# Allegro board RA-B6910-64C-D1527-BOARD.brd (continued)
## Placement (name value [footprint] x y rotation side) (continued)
C654  105  [C0402]  96.82 83.72 270 bottom
C655  104  [C0402]  91.87 94.16 90 bottom
C656  104  [C0402]  96.57 91.24 0 bottom
C657  103  [C0402]  105.08 90.86 0 bottom
C658  10uf/6.3V  [C0603]  102.92 86.84 0 bottom
C659  105  [C0402]  99.11 81.46 0 bottom
C660  105  [C0402]  99.11 82.47 0 bottom
C661  105  [C0402]  94.53 86.03 270 bottom
C662  105  [C0402]  95.42 89.84 90 bottom
C663  105  [C0402]  116.38 83.74 0 bottom
C664  105  [C0402]  100.1 87.55 0 bottom
C665  105  [C0402]  97.07 88.44 90 bottom
C666  105  [C0402]  96.69 86.41 180 bottom
C667  105  [C0402]  95.42 87.68 90 bottom
C668  105  [C0402]  92.63 87.1 180 bottom
C669  105  [C0402]  95.8 84.51 270 bottom
C670  105  [C0402]  98.73 86.33 0 bottom
C671  105  [C0402]  116.38 82.6 0 bottom
C672  105  [C0402]  99.11 83.49 0 bottom
C673  104  [C0402]  99.11 80.44 0 bottom
C674  22uF/6.3V  [C0603]  83.99 73.58 0 bottom
C675  22uF/6.3V  [C0603]  83.99 79.68 0 bottom
C676  22uF/6.3V  [C0603]  83.99 78.16 0 bottom
C677  22uF/6.3V  [C0603]  83.99 76.63 0 bottom
C678  22uF/6.3V  [C0603]  83.99 75.11 0 bottom
C679  104  [C0402]  101.9 138.35 0 top
C680  104  [C0402]  113.97 137.47 180 bottom
C681  104  [C0402]  111.17 106.1 0 bottom
C682  104  [C0402]  122.86 105.08 180 bottom
C683  104  [C0402]  102.41 130.73 0 top
C684  104  [C0402]  113.84 129.72 180 bottom
C685  104  [C0402]  111.17 110.92 0 top
C686  104  [C0402]  122.86 111.18 180 top
C687  104  [C0402]  111.17 103.56 0 top
C688  104  [C0402]  122.86 102.03 180 bottom
C689  104  [C0402]  134.41 68.5 0 top
C690  104  [C0402]  125.78 68.76 0 top
C691  104  [C0402]  125.78 68.76 0 bottom
C692  104  [C0402]  137.71 67.62 180 bottom
C693  104  [C0402]  74.34 36.25 0 top
C694  104  [C0402]  64.18 35.1 180 top
C695  104  [C0402]  124 65.71 270 top
C696  104  [C0402]  121.84 56.31 90 top
C697  104  [C0402]  126.28 105.84 180 top
C698  104  [C0402]  127.05 110.41 270 top
C699  104  [C0402]  137.46 106.35 0 top
C700  104  [C0402]  126.79 122.1 90 top
C701  104  [C0402]  146.22 77.39 270 top
C702  104  [C0402]  146.22 65.71 90 top
C703  104  [C0402]  150.8 76.38 270 bottom
C704  104  [C0402]  151.81 65.71 90 top
C713  220nF/16V  [C0402]  196.52 131.88 0 top
C714  220nF/16V  [C0402]  196.52 132.89 0 top
C715  220nF/16V  [C0402]  196.52 126.8 0 top
C716  220nF/16V  [C0402]  196.52 127.81 0 top
C717  220nF/16V  [C0402]  196.52 121.72 0 top
C718  220nF/16V  [C0402]  196.52 122.73 0 top
C719  220nF/16V  [C0402]  195.25 116.64 0 top
C720  220nF/16V  [C0402]  195.25 117.65 0 top
C721  220nF/16V  [C0402]  195.25 110.29 0 top
C722  220nF/16V  [C0402]  195.25 111.3 0 top
C723  220nF/16V  [C0402]  195.25 105.21 0 top
C724  220nF/16V  [C0402]  195.25 106.22 0 top
C725  220nF/16V  [C0402]  195.25 100.13 0 top
C726  220nF/16V  [C0402]  195.25 101.14 0 top
C727  220nF/16V  [C0402]  195.5 95.05 0 top
C728  220nF/16V  [C0402]  195.5 96.06 0 top
C729  10uf/6.3V  [C0603]  68.88 30.79 270 top
C730  103  [C0402]  200.58 139.88 0 top
C731  103  [C0402]  200.58 135.05 0 top
C732  103  [C0402]  194.23 137.59 0 bottom
C733  103  [C0402]  200.58 131.24 0 top
C734  103  [C0402]  200.58 138.86 0 top
C735  103  [C0402]  194.23 141.15 0 bottom
C736  103  [C0402]  194.23 140.13 0 bottom
C737  103  [C0402]  200.58 136.07 0 top
C738  103  [C0402]  194.23 138.61 0 bottom
C739  103  [C0402]  200.58 132.26 0 top
C740  103  [C0402]  194.23 136.07 0 bottom
C741  103  [C0402]  194.23 135.05 0 bottom
C742  103  [C0402]  128.06 110.41 270 bottom
C743  105  [C0402]  129.08 110.41 270 bottom
C744  103  [C0402]  91.23 161.72 90 bottom
C745  105  [C0402]  92.25 161.72 90 bottom
C746  X  [C0402]  119.43 16.31 270 bottom
C747  X  [C0402]  166.67 29.9 270 bottom
C748  X  [C0402]  58.47 16.82 270 bottom
C749  47uF/6.3V  [C0805]  139.37 31.42 270 bottom
C750  47uF/6.3V  [C0805]  120.95 30.53 270 bottom
C751  47uF/6.3V  [C0805]  57.32 39.93 90 top
C752  47uF/6.3V  [C0805]  59.61 39.93 90 top
C753  100uF/6.3V  [C1206]  71.29 30.53 270 bottom
C756  100uF/6.3V  [C1206]  73.83 30.53 270 bottom
C757  X  [C0603]  87.8 138.99 90 bottom
C758  10uF/6.3V  [C0402]  58.85 145.97 180 top
C759  104  [C0402]  58.85 144.96 0 top
C760  104  [C0402]  58.85 143.94 0 top
C761  104  [C0402]  96.19 81.84 180 bottom
C762  104  [C0402]  95.17 82.86 180 bottom
C763  104  [C0402]  93.06 89.21 270 bottom
C764  X  [C0603]  122.86 144.32 180 bottom
C765  X  [C0603]  82.22 119.8 180 top
C767  105  [C0402]  96.82 48.44 90 top
C768  0.1uF/25V  [C0402]  107.62 48.44 90 top
C769  0.1uF/25V  [C0402]  133.65 37.39 0 top
C770  105  [C0402]  133.65 38.4 0 top
C771  105  [C0402]  125.14 45.01 90 top
C772  0.1uF/25V  [C0402]  126.29 45.01 90 top
C773  105  [C0402]  128.32 48.69 270 top
C774  0.1uF/25V  [C0402]  129.46 48.69 270 top
C775  105  [C0402]  85.65 43.36 0 top
C776  0.1uF/25V  [C0402]  85.65 44.37 0 top
C777  105  [C0402]  58.21 30.15 0 top
C778  0.1uF/25V  [C0402]  58.21 29.01 0 top
C779  10uF/25V  [C0805]  189.02 12.37 90 top
C780  10uF/25V  [C0805]  189.02 12.37 90 bottom
C781  104  [C0603]  187.12 12.37 90 top
C783  104  [C0603]  183.18 10.47 180 bottom
C784  X  [C0603]  184.07 19.23 270 top
C785  105  [C0603]  182.67 19.23 90 top
C786  X  [C0603]  188.64 7.54 270 top
C787  103  [C0603]  181.28 19.23 90 top
C788  22uF/6.3V  [C0603]  172.64 7.54 0 bottom
C789  22uF/6.3V  [C0603]  172.64 9.07 0 bottom
C790  X  [C0603]  172.64 4.5 0 bottom
C791  104  [C0603]  172.64 6.02 0 bottom
C792  22UF  [C0603]  13.76 48.18 270 bottom
C793  22UF  [C0603]  15.92 48.18 270 bottom
C794  10uf/6.3V  [C0603]  12.37 51.61 90 bottom
C795  10uf/6.3V  [C0603]  13.76 51.61 90 bottom
C796  10uf/6.3V  [C0603]  12.37 48.18 270 bottom
C797  22UF  [C0603]  8.68 87.81 90 bottom
C798  22UF  [C0603]  20.11 86.41 90 bottom
C799  22UF  [C0603]  24.81 44.63 270 bottom
C800  22UF  [C0603]  26.72 44.63 270 bottom
C801  22UF  [C0603]  24.43 86.41 90 bottom
C802  22UF  [C0603]  6.4 87.81 90 bottom
C803  22UF  [C0603]  22.91 44.63 270 bottom
C804  22UF  [C0603]  13 44.63 270 bottom
C805  180P  [C0402]  97.58 159.56 90 top
C806  22uF  [C0805]  101.9 153.98 0 bottom
C807  104  [C0603]  101.9 156.13 0 top
C808  10uF  [C1206]  101.9 153.98 0 top
C809  22uF  [C0805]  101.9 156.26 0 bottom
C810  X  [C0603]  111.81 161.72 0 top
C811  104  [C0603]  111.17 159.31 270 top
C812  105  [C0603]  112.57 159.31 270 top
C813  104  [C0603]  107.87 156.13 180 top
C814  10uF  [C1206]  107.87 153.98 180 top
C815  22uF  [C0805]  107.87 156.13 180 bottom
C816  10uF/6.3V  [C0402]  46.27 134.8 270 top
C817  100P  [C0402]  48.81 134.8 270 top
CD1  100uf/25V  [CDNCC_6M6X7M7]  189.02 121.72 0 top
CD2  100uf/25V  [CDNCC_6M6X7M7]  189.02 129.08 0 top
CD3  100uf/25V  [CDNCC_6M6X7M7]  190.93 136.58 0 top
CD4  330uf/16V  [CDNCC_10M30X12M2]  194.48 26.85 0 top
CD6  220uF/25V  [CDNCC_0810]  191.05 46.79 90 top
CD7  220uF/25V  [CDNCC_0810]  168.19 158.42 0 top
CD8  330uF/2V  [CDRUB_7M3X4M3]  109.65 28.88 90 bottom
CD9  330uF/2V  [CDRUB_7M3X4M3]  97.46 29.13 90 bottom
CD10  220uF/25V  [CDNCC_0810]  95.68 7.04 90 top
CD11  220uF/25V  [CDNCC_0810]  106.6 7.04 90 top
CD12  330uF/2V  [CDRUB_7M3X4M3]  131.87 28.25 90 bottom
CD13  330uF/2V  [CDRUB_7M3X4M3]  144.06 41.58 180 bottom
CD14  330uF/2V  [CDRUB_7M3X4M3]  144.06 48.06 180 bottom
CD16  330uF/2V  [CDRUB_7M3X4M3]  56.43 50.25 90 top
CD17  330uF/2V  [CDRUB_7M3X4M3]  87.04 32.94 90 bottom
CD18  330uF/2V  [CDRUB_7M3X4M3]  80.69 32.82 90 bottom
CD19  220uF/25V  [CDNCC_0810]  84.5 7.04 90 top
CD20  220uF/25V  [CDNCC_0810]  172.13 6.78 180 top
COUPON1  -  [COUPON]  17.45 150.55 0 top
COUPON2  -  [COUPON]  17.57 17.45 0 top
COUPON3  -  [COUPON]  147.87 3.86 0 top
COUPON4  -  [COUPON]  196.52 154.1 0 top
D1  LS_SP190YG84_5  [LED_SMT0603]  159.56 92.76 180 top
D2  LS_SP190YG84_5  [LED_SMT0603]  94.28 127.81 270 top
D3  LS_SP190YG84_5  [LED_SMT0603]  93.01 155.75 180 top
D4  LS_SP190YG84_5  [LED_SMT0603]  138.22 70.92 0 top
D5  LS_SP190YG84_5  [LED_SMT0603]  138.22 68.89 0 top
D6  LS_SP190YG84_5  [LED_SMT0603]  138.22 74.98 0 top
D7  LS_SP190YG84_5  [LED_SMT0603]  138.22 72.95 0 top
D8  LS_SP190YG84_5  [LED_SMT0603]  67.61 137.85 180 top
D9  LS_SP190YG84_5  [LED_SMT0603]  67.61 136.07 180 top
D10  LS_SP190YG84_5  [LED_SMT0603]  67.61 134.29 180 top
D11  LS_SP190YG84_5  [LED_SMT0603]  67.61 132.51 180 top
D12  LS_SP190YG84_5  [LED_SMT0603]  67.61 130.73 180 top
D13  LS_SP190YG84_5  [LED_SMT0603]  67.61 128.96 180 top
D14  LS_SP190YG84_5  [LED_SMT0603]  67.61 127.18 180 top
D15  LS_SP190YG84_5  [LED_SMT0603]  67.61 125.4 180 top
D16  LS_SP190YG84_5  [LED_SMT0603]  60.75 149.28 270 top
D17  LS_SP190YG84_5  [LED_SMT0603]  64.94 149.15 270 top
D18  LS_SP190YG84_5  [LED_SMT0603]  68.12 149.15 270 top
D20  LS_SP190YG84_5  [LED_SMT0603]  190.8 55.55 270 top
D21  BAT54CLT1  [SOT_23]  152.07 23.17 0 bottom
D30  LS_SP190YG84_5  [LED_SMT0603]  135.94 133.27 0 top
D31  MBR0530T1G  [SOD_123]  161.84 103.91 270 top
D32  MBR0530T1G  [SOD_123]  159.94 103.91 270 top
FD1  -  [MARK]  20.62 145.34 0 top
FD3  -  [MARK]  20.62 145.34 180 bottom
FD4  -  [MARK]  177.59 157.02 180 bottom
FD5  -  [MARK]  154.1 10.85 180 bottom
FD6  -  [MARK]  11.6 17.07 180 bottom
FD10  -  [MARK]  179.12 151.56 0 top
FD11  -  [MARK]  154.1 10.85 0 top
FD12  -  [MARK]  11.6 17.07 0 top
FD13  -  [MARK_SYMBOL]  114.35 27.61 0 top
FD14  -  [MARK_SYMBOL]  126.03 13.01 0 top
J1  -  [1125_1205G0M110P1]  77.87 157.91 0 top
J3  -  [10131758]  164.28 96.15 0 top
J4  -  [HX42003_4]  198.67 13.26 90 top
J5  PUMBus test conn  [1125_1205G0M110P1]  138.98 7.16 0 top
J7  -  [10141732]  6.47 80.4 90 top
J8  -  [10141997]  20.2 46 90 top
JP1  -  [SIP_3P]  163.65 4.75 180 top
JP2  -  [SIP_3P]  163.65 9.58 180 top
L1  90/0.15A  [L0603]  197.02 81.33 0 top
L2  90/0.15A  [L0603]  197.02 82.73 0 top
L3  100/4A  [L0805]  135.3 99.11 90 bottom
L4  100/4A  [L0805]  155.62 95.68 180 top
L5  X  [L0805]  92.76 144.96 0 bottom
L6  100/4A  [L0805]  165.91 90.86 0 top
L7  3.3uH/8.5A  [MWSA0603S]  145.46 156.9 180 top
L8  1.5uH/9A  [L_7M2X6M5X3]  199.44 46.79 270 top
L9  1.5uH/9A  [L_7M2X6M5X3]  178.1 158.04 0 top
L10  4.5uH/3A  [NR6045T100M]  170.61 147.24 0 top
L11  4.5uH/3A  [NR6045T100M]  170.35 136.83 0 top
L12  4.5uH/3A  [NR6045T100M]  157.02 57.33 0 top
L13  100/4A  [L0805]  150.41 61.9 90 bottom
L14  3.3uH/8.5A  [MWSA0603S]  157.78 66.35 0 top
L15  100/4A  [L0805]  150.54 108.76 0 bottom
L16  100/4A  [L0805]  181.4 112.98 270 top
L17  80/1.5A  [L0805]  160.45 113.97 180 bottom
L18  80/1.5A  [L0805]  160.45 120.7 180 bottom
L19  80/1.5A  [L0805]  138.48 140.77 270 bottom
L20  80/1.5A  [L0805]  160.45 116.26 180 bottom
L21  200nH/50A  [L_11M50X7M00X9M20]  108.5 29.01 270 top
L22  200nH/50A  [L_11M50X7M00X9M20]  97.07 29.01 270 top
L23  0.22uH/25A  [L_7M2X6M5X3]  124.25 6.27 0 top
L24  0.22uH/25A  [L_7M2X6M5X3]  132.89 29.01 270 top
L25  0.22uH/25A  [L_7M2X6M5X3]  144.19 39.8 0 top
L26  0.22uH/25A  [L_7M2X6M5X3]  144.19 48.69 0 top
L27  3A  [L1206]  169.21 46.15 0 top
L28  200nH/50A  [L_11M50X7M00X9M20]  85.01 29.01 270 top
L29  1.5uH/9A  [L_7M2X6M5X3]  75 29.01 270 top
L30  0.22uH/25A  [L_7M2X6M5X3]  75.99 7.81 270 top
L31  100/4A  [L0805]  125.52 124 180 bottom
L32  8.2nH/800mA  [L0603]  112.95 59.23 180 bottom
L33  8.2nH/800mA  [L0603]  114.85 75.24 180 top
L35  80/1.5A  [L0805]  58.59 145.34 0 bottom
L36  X  [L_7M2X6M5X3]  183.18 5.77 0 top
L37  100/4A  [L0805]  92.76 148.01 0 bottom
NOREF  -  []  165.03 100.87 0 top
NOREF#2  -  []  187.6 2.27 90 top
NOREF#3  -  []  241.53 61.28 90 top
NOREF#4  -  []  105.2 127.43 90 top
NOREF#5  -  []  119.96 105.85 90 top
NOREF#6  -  []  198.65 141.26 90 top
NOREF#7  -  []  201.27 147.29 90 top
NOREF#8  -  []  38.2 114.93 90 top
NOREF#9  -  []  241.53 61.28 90 top
NOREF#10  -  []  118.91 98.85 90 top
NOREF#11  -  []  145.2 26.4 90 top
NOREF#12  -  []  163.92 154.08 90 top
NOREF#13  -  []  131.87 25.09 90 top
NOREF#14  -  []  66.35 116 0 top
NOREF#15  -  []  102.86 160.71 90 top
NOREF#16  -  []  28.88 140.51 90 top
NOREF#17  -  []  128.99 97.59 0 top
NOREF#18  -  []  157.04 148.08 0 top
NOREF#19  -  []  140.3 131.96 0 top
NOREF#20  -  []  16.1 75.78 90 top
NOREF#21  -  []  157.82 85.18 0 top
NOREF#22  -  []  6.47 46 0 top
NOREF#23  -  []  106.44 134.67 0 top
NOREF#24  -  []  160.96 24.18 0 top
NOREF#25  -  []  258.79 144.45 90 top
NOREF#26  -  []  189.19 62.04 90 top
NOREF#27  -  []  138.57 160.66 270 top
NOREF#28  -  []  118.91 105.58 90 top
NOREF#29  -  []  152.98 34.73 0 top
NOREF#30  -  []  174.28 94.42 0 top
NOREF#31  -  []  58.33 25.08 0 top
NOREF#32  -  []  176.11 148.64 0 top
NOREF#33  -  []  120.17 20.13 90 top
NOREF#34  -  []  141.55 68.61 90 top
NOREF#35  -  []  113.67 15.74 90 top
NOREF#36  -  []  133.95 158.8 270 top
NOREF#37  -  []  156.46 40.56 90 top
NOREF#38  -  []  148.23 143.84 0 top
NOREF#39  -  []  102.34 2.76 0 top
NOREF#40  -  []  185.42 118.32 90 top
NOREF#41  -  []  122.45 100.6 0 top
NOREF#42  -  []  163.16 60.12 0 top
NOREF#43  -  []  168.86 6.78 0 top
NOREF#44  -  []  155.09 111.03 0 top
NOREF#45  -  []  156.94 101.67 270 top
NOREF#46  -  []  156.52 48.27 90 top
NOREF#47  -  []  184.28 96.15 90 top
NOREF#48  -  []  128.99 58.09 0 top
NOREF#49  -  []  140.91 48.06 0 top
NOREF#50  -  []  140.26 43.88 0 top
NOREF#51  -  []  113.2 104.06 90 top
NOREF#52  -  []  148.61 36.3 90 top
NOREF#53  -  []  96.7 20.63 90 top
NOREF#54  -  []  2.37 56.78 90 top
NOREF#55  -  []  106.34 137.97 90 top
NOREF#56  -  []  112.67 15.74 0 top
NOREF#57  -  []  111.96 60.25 90 top
NOREF#58  -  []  87.04 29.79 90 top
NOREF#59  -  []  16.1 47.28 90 top
NOREF#60  -  []  134.57 160.66 0 top
NOREF#61  -  []  147.38 68.6 0 top
NOREF#62  -  []  111.07 142.14 90 top
NOREF#63  -  []  109.9 130.47 90 top
NOREF#64  -  []  2.37 113.78 0 top
NOREF#65  -  []  20.2 46 90 top
NOREF#66  -  []  152.76 51.46 0 top
NOREF#67  -  []  155.89 111.03 90 top
NOREF#68  -  []  147.38 68.6 90 top
NOREF#69  -  []  165.43 65.63 0 top
NOREF#70  -  []  146.45 59.69 270 top
NOREF#71  -  []  66.35 44 90 top
NOREF#72  -  []  100.73 15.74 0 top
NOREF#73  -  []  113.2 105.46 90 top
NOREF#74  -  []  20.2 46 90 top
NOREF#75  -  []  161.43 62.95 90 top
NOREF#76  -  []  59.25 37.4 0 top
NOREF#77  -  []  129.83 24.24 0 top
NOREF#78  -  []  129.62 69.76 90 top
NOREF#79  -  []  114.06 99.12 0 top
NOREF#80  -  []  186.47 121.72 0 top
NOREF#81  -  []  188.38 136.58 0 top
NOREF#82  -  []  129.59 140.64 270 top
NOREF#83  -  []  197.38 91.73 90 top
NOREF#84  -  []  119.96 99.12 90 top
NOREF#85  -  []  32.2 46.6 90 top
NOREF#86  -  []  10.57 78.03 90 top
NOREF#87  -  []  104.19 130.35 90 top
NOREF#88  -  []  130.32 31.3 90 top
NOREF#89  -  []  113.2 110.8 90 top
NOREF#90  -  []  91.41 2.76 0 top
NOREF#91  -  []  54.14 46.45 90 top
NOREF#92  -  []  156.94 102.32 270 top
NOREF#93  -  []  186.79 42.51 0 top
NOREF#94  -  []  167.03 33.72 90 top
NOREF#95  -  []  176.41 2.52 90 top
NOREF#96  -  []  163.93 100.65 0 top
NOREF#97  -  []  197.3 143.32 90 top
NOREF#98  -  []  184.01 65.63 0 top
NOREF#99  -  []  141.55 68.61 0 top
NOREF#100  -  []  170.06 67.49 90 top
NOREF#101  -  []  89.67 15.74 90 top
NOREF#102  -  []  134.49 140.15 270 top
NOREF#103  -  []  128.99 60.63 270 top
NOREF#104  -  []  202.87 151.64 0 top
NOREF#105  -  []  176.74 144.24 90 top
NOREF#106  -  []  2.37 47.28 90 top
NOREF#107  -  []  148.61 45.19 90 top
NOREF#108  -  []  152.56 51.51 0 top
NOREF#109  -  []  185.21 94.56 90 top
NOREF#110  -  []  6.47 114.8 0 top
NOREF#111  -  []  197.38 141.26 0 top
NOREF#112  -  []  132.83 106.33 0 top
NOREF#113  -  []  163.23 56.55 90 top
NOREF#114  -  []  185.61 68.47 0 top
NOREF#115  -  []  108.1 31.93 90 top
NOREF#116  -  []  -28.47 54.87 90 top
NOREF#117  -  []  152.56 42.11 0 top
NOREF#118  -  []  163.23 18.55 90 top
NOREF#119  -  []  106.06 147.5 0 top
NOREF#120  -  []  59.08 20.13 90 top
NOREF#121  -  []  96.18 20.63 90 top
NOREF#122  -  []  181.36 146.1 90 top
NOREF#123  -  []  189.23 21.6 90 top
NOREF#124  -  []  84.5 3.76 90 top
NOREF#125  -  []  182.55 16.01 0 top
NOREF#126  -  []  165.03 100.87 0 top
NOREF#127  -  []  88.76 23.76 90 top
NOREF#128  -  []  164.81 70.03 0 top
NOREF#129  -  []  174.28 94.42 0 top
NOREF#130  -  []  10.57 97.53 90 top
NOREF#131  -  []  112.26 23.76 90 top
NOREF#132  -  []  160.22 143.84 270 top
NOREF#133  -  []  77.76 11.93 90 top
NOREF#134  -  []  63.43 19.98 90 top
NOREF#135  -  []  176.48 133.83 90 top
NOREF#136  -  []  181.78 94.42 0 top
NOREF#137  -  []  181.53 100.87 0 top
NOREF#138  -  []  175.86 138.23 0 top
NOREF#139  -  []  140.26 45.76 90 top
NOREF#140  -  []  157.19 85.78 0 top
NOREF#141  -  []  135.93 103.23 90 top
NOREF#142  -  []  129.1 134.78 0 top
NOREF#143  -  []  163.28 94.56 90 top
NOREF#144  -  []  88.3 5.2 90 top
NOREF#145  -  []  128.35 42.43 90 top
NOREF#146  -  []  20.2 46 0 top
NOREF#147  -  []  163.92 162.68 0 top
NOREF#148  -  []  142.45 59.69 0 top
NOREF#149  -  []  14.47 42.65 90 top
NOREF#150  -  []  67.04 36.16 0 top
NOREF#151  -  []  181.11 135.69 90 top
NOREF#152  -  []  151.85 99.83 0 top
NOREF#153  -  []  124.52 19.98 90 top
NOREF#154  -  []  7.49 144.68 0 top
NOREF#155  -  []  176.48 133.83 0 top
NOREF#156  -  []  139.51 133.19 0 top
NOREF#157  -  []  166.28 38.67 0 top
NOREF#158  -  []  164.92 158.42 0 top
NOREF#159  -  []  162.22 28.08 270 top
NOREF#160  -  []  23.3 133.4 0 top
NOREF#161  -  []  85.49 35.99 90 top
NOREF#162  -  []  133.62 102.03 270 top
NOREF#163  -  []  2.37 75.78 90 top
NOREF#164  -  []  115.23 105.59 90 top
NOREF#165  -  []  101.73 15.74 90 top
NOREF#166  -  []  -28.47 54.87 0 top
NOREF#167  -  []  189.23 32.1 0 top
NOREF#168  -  []  95.68 3.76 90 top
NOREF#169  -  []  99.76 25.33 90 top
NOREF#170  -  []  135.33 69.65 90 top
NOREF#171  -  []  182.52 154.54 90 top
NOREF#172  -  []  125.14 141.12 270 top
NOREF#173  -  []  197.28 89.3 0 top
NOREF#174  -  []  112.26 34.26 270 top
NOREF#175  -  []  140.3 131.96 90 top
NOREF#176  -  []  154.13 69.75 0 top
NOREF#177  -  []  10.57 57.53 90 top
NOREF#178  -  []  141.26 133.19 90 top
NOREF#179  -  []  88.67 15.74 0 top
NOREF#180  -  []  161.22 145.14 270 top
NOREF#181  -  []  105.17 142.79 0 top
NOREF#182  -  []  114.06 110.4 0 top
NOREF#183  -  []  113.83 105.58 90 top
NOREF#184  -  []  24.3 47.03 90 top
NOREF#185  -  []  108.5 33.56 270 top
NOREF#186  -  []  141.82 57.84 270 top
NOREF#187  -  []  96.18 20.63 0 top
NOREF#188  -  []  163.23 38.55 90 top
NOREF#189  -  []  189.19 62.04 90 top
NOREF#190  -  []  163.78 55.72 0 top
NOREF#191  -  []  102.34 2.76 0 top
NOREF#192  -  []  6.47 114.8 0 top
NOREF#193  -  []  189.19 62.04 0 top
NOREF#194  -  []  20.2 46 90 top
NOREF#195  -  []  119.42 25.08 0 top
NOREF#196  -  []  80.24 2.76 0 top
NOREF#197  -  []  85.01 33.56 270 top
NOREF#198  -  []  66.35 44 0 top
NOREF#199  -  []  201.19 91.73 90 top
NOREF#200  -  []  87.31 26.4 90 top
NOREF#201  -  []  199.92 91.73 0 top
NOREF#202  -  []  -1.85 114.18 0 top
NOREF#203  -  []  185.61 61.28 0 top
NOREF#204  -  []  107.58 157.57 90 top
NOREF#205  -  []  41.3 17.09 90 top
NOREF#206  -  []  141.82 55.3 0 top
NOREF#207  -  []  124.37 20.73 90 top
NOREF#208  -  []  6.47 114.8 90 top
NOREF#209  -  []  183.28 94.42 90 top
NOREF#210  -  []  137.62 22.01 0 top
NOREF#211  -  []  179.03 100.87 0 top
NOREF#212  -  []  82.99 29.02 90 top
NOREF#213  -  []  187.29 112.73 90 top
NOREF#214  -  []  117.04 60.25 0 top
NOREF#215  -  []  104.31 137.85 90 top
NOREF#216  -  []  34.38 119.38 0 top
NOREF#217  -  []  17.32 133.4 0 top
NOREF#218  -  []  160.54 158.88 270 top
NOREF#219  -  []  165.28 94.42 90 top
NOREF#220  -  []  89.34 29.14 90 top
NOREF#221  -  []  110.95 134.65 90 top
NOREF#222  -  []  147.11 69.65 0 top
NOREF#223  -  []  84.12 20.63 0 top
NOREF#224  -  []  156.41 156.5 90 top
NOREF#225  -  []  185.67 11.39 90 top
NOREF#226  -  []  152.76 42.06 0 top
NOREF#227  -  []  35.99 146.61 0 top
NOREF#228  -  []  129.62 62.49 0 top
NOREF#229  -  []  6.47 46 90 top
NOREF#230  -  []  180.69 11.39 0 top
NOREF#231  -  []  90.85 42.43 0 top
NOREF#232  -  []  103.58 157.57 0 top
NOREF#233  -  []  184.01 64.11 90 top
NOREF#234  -  []  185.62 132.48 0 top
NOREF#235  -  []  186.47 129.08 0 top
NOREF#236  -  []  108.64 20.63 90 top
NOREF#237  -  []  111.83 129.29 90 top
NOREF#238  -  []  16.1 113.78 0 top
NOREF#239  -  []  88.76 34.26 270 top
NOREF#240  -  []  165.43 65.63 90 top
NOREF#241  -  []  171.23 34.32 90 top
NOREF#242  -  []  140.91 41.58 0 top
NOREF#243  -  []  155.92 157.02 270 top
NOREF#244  -  []  154.93 66.35 0 top
NOREF#245  -  []  187.29 114 0 top
NOREF#246  -  []  129.98 115.03 90 top
NOREF#247  -  []  20.2 46 0 top
NOREF#248  -  []  56.43 47.1 90 top
NOREF#249  -  []  10.57 47.03 90 top
NOREF#250  -  []  167.81 3.48 0 top
NOREF#251  -  []  142.02 69.65 90 top
NOREF#252  -  []  6.47 46 90 top
NOREF#253  -  []  14.47 42.65 0 top
NOREF#254  -  []  133.88 16.24 90 top
NOREF#255  -  []  140.26 50.36 0 top
NOREF#256  -  []  108.12 20.63 0 top
NOREF#257  -  []  191.2 116.43 0 top
NOREF#258  -  []  122.35 141.78 0 top
NOREF#259  -  []  147.23 145.14 0 top
NOREF#260  -  []  191.1 114 0 top
NOREF#261  -  []  111.95 25.08 90 top
NOREF#262  -  []  63.28 20.73 90 top
NOREF#263  -  []  156.46 49.96 90 top
NOREF#264  -  []  16.1 78.28 90 top
NOREF#265  -  []  188.74 59.38 90 top
NOREF#266  -  []  201.19 91.73 90 top
NOREF#267  -  []  105.58 143.05 0 top
NOREF#268  -  []  57.98 53.3 90 top
NOREF#269  -  []  164.28 96.15 0 top
NOREF#270  -  []  149.11 156.5 0 top
NOREF#271  -  []  140.26 39.28 90 top
NOREF#272  -  []  95.91 32.18 90 top
NOREF#273  -  []  199.29 143.69 0 top
NOREF#274  -  []  119.57 23.93 90 top
NOREF#275  -  []  109.65 25.73 90 top
NOREF#276  -  []  156.54 158.88 0 top
NOREF#277  -  []  105.96 130.23 0 top
NOREF#278  -  []  191.05 43.51 90 top
NOREF#279  -  []  187.53 139.98 0 top
NOREF#280  -  []  44.37 142.26 0 top
NOREF#281  -  []  241.53 68.47 90 top
NOREF#282  -  []  72.94 24.24 0 top
NOREF#283  -  []  122.25 65.96 90 top
NOREF#284  -  []  97.46 25.98 90 top
NOREF#285  -  []  165.28 94.42 0 top
NOREF#286  -  []  163.78 55.72 90 top
NOREF#287  -  []  106.6 3.76 90 top
NOREF#288  -  []  106.21 130.48 90 top
NOREF#289  -  []  80.69 29.67 90 top
NOREF#290  -  []  125.14 141.12 270 top
NOREF#291  -  []  190.36 26.85 0 top
NOREF#292  -  []  6.47 46 90 top
NOREF#293  -  []  151.25 100.37 0 top
NOREF#294  -  []  66.35 44 0 top
NOREF#295  -  []  141.28 69.66 0 top
NOREF#296  -  []  91.41 2.76 0 top
NOREF#297  -  []  70.81 32.49 90 top
NOREF#298  -  []  2.37 78.28 90 top
NOREF#299  -  []  20.2 114.8 90 top
NOREF#300  -  []  2.37 100.78 90 top
NOREF#301  -  []  113.83 98.85 90 top
NOREF#302  -  []  140.97 24.18 0 top
NOREF#303  -  []  67.71 35.59 0 top
NOREF#304  -  []  -3.85 140.38 0 top
NOREF#305  -  []  133.95 156.26 0 top
NOREF#306  -  []  185.42 125.68 90 top
NOREF#307  -  []  124.21 135.25 0 top
NOREF#308  -  []  142.61 156.9 0 top
NOREF#309  -  []  24.3 78.03 90 top
NOREF#310  -  []  119.96 109.75 90 top
NOREF#311  -  []  105.05 135.3 0 top
NOREF#312  -  []  186.79 42.51 0 top
NOREF#313  -  []  156.35 102.93 0 top
NOREF#314  -  []  118.91 105.57 90 top
NOREF#315  -  []  163.93 100.65 0 top
NOREF#316  -  []  80.24 2.76 0 top
NOREF#317  -  []  152.32 75.36 90 top
NOREF#318  -  []  36.37 140.51 0 top
NOREF#319  -  []  58.48 23.93 90 top
NOREF#320  -  []  126.88 118.13 0 top
NOREF#321  -  []  32.2 114.2 90 top
NOREF#322  -  []  79.14 35.87 90 top
NOREF#323  -  []  133.62 62.49 270 top
NOREF#324  -  []  117.31 59.2 90 top
NOREF#325  -  []  110.02 137.96 90 top
NOREF#326  -  []  155.92 154.48 0 top
NOREF#327  -  []  136.19 69.66 90 top
NOREF#328  -  []  49.45 138.26 90 top
NOREF#329  -  []  128.57 74.59 0 top
NOREF#330  -  []  129.62 96.95 0 top
NOREF#331  -  []  128.67 2.77 90 top
NOREF#332  -  []  134.17 24.44 90 top
NOREF#333  -  []  181.28 10.76 90 top
NOREF#334  -  []  75.48 16.24 0 top
NOREF#335  -  []  129.05 105.75 0 top
NOREF#336  -  []  108.12 20.63 90 top
NOREF#337  -  []  76.99 16.24 90 top
NOREF#338  -  []  132.38 16.24 0 top
NOREF#339  -  []  171.38 33.57 90 top
NOREF#340  -  []  176.14 128.98 90 top
NOREF#341  -  []  134.66 11.93 90 top
NOREF#342  -  []  111.45 142.12 90 top
NOREF#343  -  []  84.63 20.63 90 top
NOREF#344  -  []  144.45 37.4 90 top
NOREF#345  -  []  197.28 89.3 90 top
NOREF#346  -  []  23.3 133.4 0 top
NOREF#347  -  []  179.28 94.42 0 top
NOREF#348  -  []  146.49 75.37 90 top
NOREF#349  -  []  133.3 69.77 90 top
NOREF#350  -  []  128.57 73.94 90 top
NOREF#351  -  []  196.88 89.73 0 top
NOREF#352  -  []  24.3 75.53 90 top
NOREF#353  -  []  195.94 42.37 0 top
NOREF#354  -  []  166.43 37.52 90 top
NOREF#355  -  []  187.33 133.18 90 top
NOREF#356  -  []  114.06 105.85 0 top
NOREF#357  -  []  176.74 144.24 0 top
NOREF#358  -  []  183.28 94.42 90 top
NOREF#359  -  []  165.03 100.87 0 top
NOREF#360  -  []  105.2 149.66 270 top
NOREF#361  -  []  -32.7 17.09 0 top
NOREF#362  -  []  34.97 133.53 270 top
NOREF#363  -  []  168.41 57.58 90 top
NOREF#364  -  []  122.35 133.02 0 top
NOREF#365  -  []  156.52 38.88 90 top
NOREF#366  -  []  84.12 20.63 90 top
NOREF#367  -  []  165.28 94.42 0 top
NOREF#368  -  []  127.45 114.35 90 top
NOREF#369  -  []  48.81 137.63 90 top
NOREF#370  -  []  117.31 59.2 0 top
NOREF#371  -  []  165.03 100.87 0 top
NOREF#372  -  []  10.57 75.53 90 top
NOREF#373  -  []  201.27 148.81 0 top
NOREF#374  -  []  185.62 125.12 0 top
NOREF#375  -  []  164.28 96.15 90 top
OSC1  50MHZ  [SMD5X7]  142.92 100 0 top
OSC2  24MHz  [D3SX24E000008E]  140.38 134.29 270 top
OSC3  25.000625MHz  [OSC_SMD3M2X2M5]  170.73 125.65 0 top
OSC4  25.000625MHz  [OSC_SMD3M2X2M5]  119.43 69.01 0 top
OSC5  25.000625MHz  [OSC_SMD3M2X2M5]  108 108.76 270 top
OSC6  25MHZ  [SMD5X7]  64.94 142.8 0 top
Q1  SM12  [SOT_23]  198.42 86.03 180 bottom
Q2  2N7002  [SOT_23]  159.94 96.32 270 top
Q3  2N7002  [SOT_23]  159.94 96.32 270 bottom
Q4  SM12  [SOT_23]  198.42 86.03 0 top
Q5  2N7002  [SOT_23]  93.01 152.45 180 top
Q6  2N7002  [SOT_23]  91.11 126.42 270 bottom
Q7  MMST3906  [SOT_23]  60.37 149.15 270 bottom
Q8  MMST3906  [SOT_23]  68.25 149.15 90 bottom
Q9  MMST3906  [SOT_23]  64.31 149.15 90 bottom
Q10  MMBT3904LT1G  [SOT_23]  14.65 91.36 270 bottom
Q11  MMBT3904LT1G  [SOT_23]  14.27 85.78 180 bottom
Q14  MMST3906  [SOT_23]  170.61 98.48 90 bottom
Q15  MMBT3904LT1G  [SOT_23]  189.15 147.37 270 top
Q16  MMBT3904LT1G  [SOT_23]  193.21 147.37 270 top
Q17  MMBT3904LT1G  [SOT_23]  189.15 147.37 270 bottom
Q18  MMBT3904LT1G  [SOT_23]  193.21 147.37 270 bottom
Q19  MMBT3904LT1G  [SOT_23]  127.94 160.58 90 bottom
Q20  MMBT3904LT1G  [SOT_23]  127.94 160.58 270 top
Q21  MMBT3904LT1G  [SOT_23]  123.87 160.58 90 top
Q22  MMBT3904LT1G  [SOT_23]  123.87 160.58 270 bottom
Q23  MMBT3904LT1G  [SOT_23]  95.17 121.59 90 bottom
Q24  MMBT3904LT1G  [SOT_23]  86.28 117.4 270 bottom
Q25  MMBT3904LT1G  [SOT_23]  82.34 117.4 270 bottom
Q26  MMBT3904LT1G  [SOT_23]  95.04 126.42 90 bottom
Q27  MMBT3904LT1G  [SOT_23]  179.12 68.63 0 bottom
Q28  MMBT3904LT1G  [SOT_23]  179.12 64.57 180 bottom
Q29  MMBT3904LT1G  [SOT_23]  156 74.6 0 bottom
Q30  MMBT3904LT1G  [SOT_23]  160.7 74.6 0 bottom
Q33  MMBT3904LT1G  [SOT_23]  78.66 160.07 180 bottom
Q34  MMBT3904LT1G  [SOT_23]  95.17 151.82 180 bottom
Q35  2N7002  [SOT_23]  118.79 152.83 90 top
Q36  2N7002  [SOT_23]  76.88 118.15 270 top
Q37  MMBT3904LT1G  [SOT_23]  58.34 134.8 180 top
Q38  MMBT3904LT1G  [SOT_23]  58.34 130.73 0 top
Q39  MMBT3904LT1G  [SOT_23]  50.08 131.12 270 top
Q40  APL431LAAC_TRG  [SOT_23]  45.89 131.12 270 top
Q41  MMBT3904LT1G  [SOT_23]  47.67 149.53 270 top
R1  1K  [R0402]  195.5 85.52 90 top
R2  560  [R0402]  160.32 92.51 180 bottom
R3  33  [R0402]  199.94 83.49 180 bottom
R4  10K_1%  [R0402]  157.91 93.52 0 bottom
R5  10K_1%  [R0402]  160.32 93.52 180 bottom
R6  33  [R0402]  157.91 92.51 0 bottom
R7  1K  [R0402]  199.94 82.22 180 top
R8  560  [R0402]  95.55 129.21 0 bottom
R9  33  [R0402]  201.34 85.27 90 top
R10  560  [R0402]  93.01 157.53 180 top
R11  22  [R0402]  89.45 125.65 90 top
R12  22  [R0402]  86.41 147.5 90 bottom
R13  4.7K  [R0402]  87.42 147.5 270 bottom
R14  4.7K  [R0402]  90.47 125.65 270 top
R15  330  [R0402]  139.49 71.17 180 bottom
R16  330  [R0402]  141.65 71.17 0 bottom
R17  330  [R0402]  139.49 75.24 180 bottom
R18  330  [R0402]  139.49 73.2 180 bottom
R19  33_1%  [R0402]  61.77 37.14 0 top
R20  33_1%  [R0402]  61.77 36.12 0 top
R21  1K_1%  [R0402]  148.76 91.24 270 top
R22  1K_1%  [R0402]  143.68 91.24 270 top
R23  1K_1%  [R0402]  151.68 96.19 0 top
R24  2.49K_1%  [R0402]  154.48 90.73 0 top
R25  1K_1%  [R0402]  152.83 93.9 270 top
R26  0  [R0402]  146.73 91.24 270 top
R27  0  [R0402]  145.72 91.24 270 top
R28  0  [R0402]  151.68 97.21 0 top
R29  0  [R0402]  154.61 93.78 0 top
R30  0  [R0402]  150.8 93.9 270 top
R31  7.15K_1%  [R0402]  154.48 91.75 180 top
R32  1K_1%  [R0402]  152.83 91.24 270 top
R33  1K_1%  [R0402]  143.68 93.9 270 top
R34  3.3K_1%  [R0402]  163.75 129.72 180 top
R35  7.15K_1%  [R0402]  172.26 129.72 90 top
R36  1K_1%  [R0402]  149.78 93.9 270 top
R37  0  [R0402]  149.78 91.24 270 top
R38  0  [R0402]  146.73 93.9 270 top
R39  0  [R0402]  161.21 131.75 0 top
R40  0  [R0402]  169.21 129.72 90 top
R41  0  [R0402]  147.75 93.9 270 top
R42  620_1%  [R0402]  150.8 91.24 90 top
R43  620_1%  [R0402]  144.7 93.9 90 top
R44  1K_1%  [R0402]  163.75 131.75 0 top
R45  820_1%  [R0402]  171.24 129.72 270 top
R46  X  [R0402]  167.43 120.96 90 bottom
R47  X  [R0402]  164.38 120.96 90 bottom
R48  33  [R0402]  82.47 108.76 270 bottom
R49  33  [R0402]  166.42 120.96 90 bottom
R50  33  [R0402]  165.4 120.96 90 bottom
R51  0  [R0402]  140.25 114.61 270 bottom
R52  33  [R0402]  88.06 142.04 0 bottom
R53  33  [R0402]  137.56 114.35 0 bottom
R54  33  [R0402]  149.4 98.22 0 top
R55  4.7K  [R0402]  153.46 101.91 180 bottom
R56  33  [R0402]  157.02 100.89 180 bottom
R57  22  [R0402]  148.51 103.94 0 top
R58  33  [R0402]  157.02 101.91 180 bottom
R59  0  [R0402]  82.72 150.8 270 top
R60  33  [R0402]  71.17 136.07 180 bottom
R61  33  [R0402]  94.28 130.86 0 top
R63  33  [R0402]  96.69 101.02 270 bottom
R64  0  [R0402]  83.74 150.8 270 top
R65  33  [R0402]  94.28 134.93 0 top
R66  33  [R0402]  71.17 139.12 180 bottom
R67  33  [R0402]  71.17 140.13 180 bottom
R68  4.7K  [R0402]  71.17 138.1 180 bottom
R69  4.7K  [R0402]  71.17 133.02 180 bottom
R70  10K_1%  [R0402]  83.36 125.65 90 bottom
R71  X  [R0402]  94.28 131.88 0 top
R72  0  [R0402]  94.28 132.89 0 top
R73  10K_1%  [R0402]  80.44 129.85 270 bottom
R74  0  [R0402]  71.17 135.05 180 bottom
R75  10K_1%  [R0402]  71.04 131.62 180 bottom
R76  10K_1%  [R0402]  71.04 129.59 180 bottom
R77  10K_1%  [R0402]  85.39 125.65 270 bottom
R78  10K_1%  [R0402]  81.45 129.85 270 bottom
R79  0  [R0402]  71.17 137.08 180 bottom
R80  0  [R0402]  71.17 134.04 180 bottom
R81  33  [R0402]  94.28 133.91 0 bottom
R82  0  [R0402]  71.04 130.61 180 bottom
R83  0  [R0402]  88.44 125.65 270 top
R84  0  [R0402]  79.29 125.65 270 top
R85  0  [R0402]  84.37 125.65 270 top
R86  0  [R0402]  86.41 125.65 270 top
R87  0  [R0402]  87.42 125.65 270 top
R88  0  [R0402]  75.23 125.65 270 top
R89  0  [R0402]  76.25 125.65 270 top
R90  0  [R0402]  77.26 125.65 270 top
R91  0  [R0402]  78.28 125.65 270 top
R92  0  [R0402]  80.31 125.65 270 top
R93  0  [R0402]  81.33 125.65 270 top
R94  10K_1%  [R0402]  82.34 125.65 270 top
R95  10K_1%  [R0402]  77.9 129.85 270 bottom
R96  560  [R0402]  64.05 137.85 0 top
R97  560  [R0402]  64.05 136.07 0 top
R98  33  [R0402]  103.81 124.51 90 bottom
R99  560  [R0402]  64.05 134.29 0 top
R100  560  [R0402]  64.05 132.51 0 top
R101  560  [R0402]  64.05 130.73 0 top
R102  560  [R0402]  64.05 128.96 0 top
R103  560  [R0402]  64.05 127.18 0 top
R104  560  [R0402]  64.05 125.4 0 top
R105  1K  [R0402]  79.42 129.85 270 bottom
R106  4.7K  [R0402]  91.99 136.96 0 bottom
R107  4.7K  [R0402]  91.99 138.35 0 bottom
R108  1K  [R0402]  82.47 129.85 270 bottom
R109  10K_1%  [R0402]  79.68 150.8 90 top
R110  10K_1%  [R0402]  77.39 150.8 90 top
R111  10K_1%  [R0402]  73.07 150.8 90 top
R112  X  [R0402]  81.71 150.8 90 top
R113  22  [R0402]  91.99 135.94 0 bottom
R114  100  [R0402]  74.09 150.8 90 top
R115  33  [R0402]  75.36 150.8 90 top
R116  100  [R0402]  78.41 150.8 90 top
R117  100  [R0402]  80.69 150.8 90 top
R118  330  [R0402]  59.1 150.29 90 top
R119  1K  [R0402]  62.28 148.01 90 top
R120  1K  [R0402]  59.1 148.13 90 top
R121  330  [R0402]  63.42 148.01 270 top
R122  1K  [R0402]  69.64 150.17 90 top
R123  1K  [R0402]  69.64 148.01 90 top
R124  330  [R0402]  66.59 148.13 270 top
R125  1K  [R0402]  63.42 150.17 270 top
R126  1K  [R0402]  62.28 150.17 90 top
R127  0  [R0402]  10.21 69.52 270 bottom
R129  0  [R0402]  19.35 43.36 270 bottom
R131  0  [R0402]  18.21 43.36 270 bottom
R133  4.7K  [R0402]  15.16 88.44 0 bottom
R134  4.7K  [R0402]  14.27 94.41 0 bottom
R137  1K  [R0402]  12.62 78.66 90 bottom
R138  1K  [R0402]  13.13 82.73 90 bottom
R139  X  [R0402]  24.3 68.25 180 bottom
R140  X  [R0402]  21.89 47.93 90 bottom
R142  0  [R0402]  26.84 49.2 0 bottom
R145  0  [R0402]  122.22 112.95 0 top
R146  0  [R0402]  124.51 112.95 180 top
R147  0  [R0402]  122.22 116 180 top
R148  0  [R0402]  122.22 117.02 180 top
R149  0  [R0402]  122.22 120.07 180 top
R150  0  [R0402]  122.22 119.05 180 top
R151  0  [R0402]  111.3 127.56 270 bottom
R152  0  [R0402]  117.27 141.4 0 top
R159  0  [R0603]  168.96 94.54 90 bottom
R160  0  [R0603]  170.35 94.54 90 bottom
R161  0  [R0603]  171.75 94.54 90 bottom
R162  0  [R0603]  173.15 94.54 90 bottom
R163  X  [R0402]  178.99 90.73 270 top
R164  1K  [R0402]  182.04 101.02 270 bottom
R165  0  [R0402]  180.01 90.73 270 top
R166  330  [R0402]  189.28 55.55 90 top
R167  1K  [R0402]  167.81 97.97 270 bottom
R168  1K  [R0402]  166.8 97.97 270 bottom
R169  0  [R0402]  183.94 66.6 0 bottom
R170  0  [R0402]  183.94 67.62 0 bottom
R171  0  [R0402]  183.94 65.58 0 bottom
R172  0  [R0402]  192.96 80.44 0 top
R173  0  [R0402]  192.96 81.46 180 top
R174  0  [R0402]  184.7 80.95 0 top
R175  0  [R0402]  192.96 84.89 180 top
R176  0  [R0402]  185.47 84.25 0 top
R177  0  [R0402]  182.92 86.03 0 top
R178  0  [R0402]  185.34 87.17 0 top
R179  0  [R0402]  192.96 93.65 180 top
R180  0  [R0402]  187.88 92.41 180 top
R181  0  [R0402]  193.34 96.83 180 top
R182  0  [R0402]  184.2 98.22 0 bottom
R183  0  [R0402]  189.28 98.22 180 top
R184  0  [R0402]  184.2 99.24 0 bottom
R185  10K_1%  [R0402]  193.34 97.84 0 top
R186  0  [R0402]  189.28 99.24 180 top
R187  0  [R0402]  184.2 100.25 0 bottom
R188  0  [R0402]  184.2 101.27 0 bottom
R189  0  [R0402]  184.2 102.29 0 bottom
R190  0  [R0402]  193.09 101.91 0 top
R191  10K_1%  [R0402]  193.09 102.92 180 top
R192  0  [R0402]  185.34 104.7 180 top
R193  0  [R0402]  185.34 105.72 180 top
R194  560  [R0402]  185.34 109.78 180 top
R195  0  [R0402]  185.34 106.73 0 top
R196  560  [R0402]  185.34 110.8 0 top
R197  0  [R0402]  185.34 108.76 0 top
R198  0  [R0402]  185.34 107.75 180 top
R199  560  [R0402]  185.34 111.81 0 top
R200  0  [R0805]  31.16 30.91 180 top
R201  X  [R0402]  27.73 27.86 270 top
R202  10K_1%  [R0603]  35.1 31.04 180 top
R203  100K_1%  [R0603]  31.03 27.86 90 top
R204  X  [R0402]  28.75 27.86 90 top
R205  0  [R0402]  29.76 27.86 90 top
R206  10K_1%  [R0603]  35.1 33.83 0 top
R207  10K_1%  [R0603]  136.95 161.6 0 top
R208  0  [R0402]  134.16 160.71 0 bottom
R209  10K_1%  [R0603]  133.78 158.04 180 bottom
R210  3.01K_1%  [R0603]  133.9 161.6 180 top
R211  3.01K_1%  [R0603]  133.78 156.64 0 bottom
R212  X  [R1206]  142.67 154.86 180 bottom
R213  10K_1%  [R0402]  193.34 33.45 90 top
R214  0  [R0402]  192.32 33.45 270 top
R215  5.6K_1%  [R0603]  189.15 33.45 0 top
R216  X  [R0805]  186.23 30.15 0 top
R217  300_1%  [R0603]  186.23 32.06 0 top
R218  300  [R0603]  189.15 36.25 180 top
R219  2.2K_1%  [R0603]  189.15 34.85 180 top
R220  10K_1%  [R0402]  194.36 33.45 90 top
R221  10K  [R0603]  189.15 37.64 0 top
R222  80.6K_1%  [R0603]  189.15 39.04 180 top
R223  0  [R0603]  185.34 39.17 180 top
R224  1  [R0805]  200.2 40.06 0 top
R225  10K_1%  [R0402]  189.78 154.99 180 top
R226  3.3K_1%  [R0402]  191.05 152.71 90 top
R227  5.6K_1%  [R0603]  187.37 152.71 90 top
R228  300  [R0603]  188.77 152.71 270 top
R229  15K_1%  [R0402]  190.04 152.71 270 top
R230  10K  [R0603]  184.58 152.71 90 top
R231  80.6K_1%  [R0603]  183.18 152.71 270 top
R232  0  [R0603]  182.8 156.64 180 bottom
R233  X  [R0805]  181.66 161.72 180 bottom
R234  0  [R0402]  192.32 154.99 180 top
R235  10K_1%  [R0402]  193.98 154.48 270 top
R236  22K_1%  [R0805]  152.45 161.72 0 top
R237  10K_1%  [R0402]  159.43 162.36 0 top
R238  4.7K  [R0402]  165.15 152.96 180 top
R239  X  [R0805]  152.45 159.44 0 top
R240  47K_1%  [R0805]  152.45 157.15 0 top
R241  1K  [R0402]  161.59 162.36 180 top
R242  0  [R0402]  184.96 143.18 180 top
R243  17.4K_1%  [R0805]  184.96 144.96 180 bottom
R244  4.7K  [R0402]  190.29 150.42 0 top
R245  10K_1%  [R0402]  188.26 150.42 180 top
R246  30.1K_1%  [R0805]  184.96 144.96 180 top
R247  10K_1%  [R0402]  184.96 142.16 180 top
R248  X  [R0603]  184.96 146.86 180 bottom
R249  X  [R1206]  175.69 151.31 180 bottom
R250  1K  [R0402]  189.15 144.45 0 top
R251  10K_1%  [R0402]  188.26 150.42 180 bottom
R252  0  [R0402]  182.16 132 90 top
R253  4.7K  [R0402]  190.29 150.42 0 bottom
R254  10K_1%  [R0603]  184.32 138.35 180 top
R255  10K_1%  [R0402]  181.15 132 270 top
R256  20K_1%  [R0603]  184.32 134.16 0 top
R257  X  [R0603]  184.32 135.56 180 top
R258  1K  [R0402]  193.21 144.58 0 bottom
R259  X  [R1206]  177.47 139.5 0 bottom
R260  X  [R0603]  126.41 53.65 270 top
R261  3.01K_1%  [R0603]  127.81 53.65 90 top
R262  10K_1%  [R0402]  137.08 62.28 0 bottom
R263  4.7K  [R0402]  137.08 60.25 180 bottom
R264  2.67K_1%  [R0603]  129.21 53.65 90 top
R265  1K  [R0402]  137.08 61.27 0 bottom
R266  4.7K  [R0402]  121.33 161.72 90 top
R267  4.7K  [R0402]  121.33 159.56 270 top
R268  4.7K  [R0402]  131.11 160.96 180 bottom
R269  10K_1%  [R0402]  131.11 159.82 180 bottom
R270  10  [R0402]  122.35 146.86 0 top
R271  1K  [R0402]  131.11 158.93 180 top
R272  1K  [R0402]  131.11 160.96 0 top
R273  1K  [R0402]  124.25 156.52 0 top
R274  4.7K  [R0402]  131.11 159.94 180 top
R275  10K_1%  [R0402]  122.35 144.83 180 top
R276  1K  [R0402]  124.25 157.53 180 top
R277  4.7K  [R0402]  97.58 126.04 90 bottom
R278  10K_1%  [R0402]  97.71 122.86 270 bottom
R279  4.7K  [R0402]  82.72 120.45 0 bottom
R280  4.7K  [R0402]  79.55 120.71 270 top
R281  10  [R0402]  79.55 118.55 270 top
R282  1K  [R0402]  88.57 116.26 270 top
R283  1K  [R0402]  84.88 120.45 180 bottom
R284  1K  [R0402]  88.57 127.56 90 bottom
R285  4.7K  [R0402]  87.55 116.26 270 top
R286  10K_1%  [R0402]  82.34 118.14 270 top
R287  0  [R0402]  168.32 53.26 90 top
R288  1.6K_1%  [R0402]  171.75 63.68 180 top
R289  4.7K  [R0402]  180.39 71.17 180 bottom
R290  10K_1%  [R0402]  178.23 71.17 180 bottom
R291  10K_1%  [R0402]  167.31 53.26 90 top
R292  1.3K_1%  [R0402]  171.75 62.66 0 top
R293  X  [R0603]  171.75 61.39 180 top
R294  1K  [R0402]  175.69 64.44 0 bottom
R295  X  [R1206]  166.16 62.28 0 bottom
R296  1.5K_1%  [R0402]  175.69 63.42 180 bottom
R297  X  [R0603]  142.29 62.92 180 bottom
R298  4.99K_1%  [R0402]  142.29 64.19 180 bottom
R299  10K_1%  [R0402]  150.29 60.88 0 top
R300  4.7K  [R0402]  150.29 58.85 180 top
R301  3.09K_1%  [R0402]  142.29 60.12 0 bottom
R302  1K  [R0402]  150.29 59.87 0 top
R303  0  [R0402]  173.4 65.96 180 top
R304  1.15k_1%  [R0603]  173.53 68.63 180 top
R305  4.7K  [R0402]  157.02 77.27 0 bottom
R306  10K_1%  [R0402]  154.73 77.27 180 bottom
R307  10K_1%  [R0402]  173.4 64.95 180 top
R308  3.01K_1%  [R0603]  173.53 70.03 0 top
R309  X  [R1206]  169.85 72.44 0 top
R310  1K  [R0402]  160.57 77.27 0 bottom
R311  22K_1%  [R0402]  164.76 14.66 0 top
R312  22K_1%  [R0402]  163.14 14.15 270 top
R313  0  [R0402]  161.11 14.15 90 top
R314  1K  [R0402]  159.94 14.15 90 top
R315  1K  [R0402]  158.92 14.15 90 top
R316  1K  [R0402]  155.49 24.18 180 bottom
R317  120K_1%  [R0402]  121.33 73.33 90 top
R318  X  [R0402]  121.59 76.38 270 top
R319  4.7K  [R0402]  122.6 76.38 270 top
R320  X  [R0402]  122.35 73.33 90 top
R321  4.7K  [R0402]  120.57 76.38 270 top
R322  X  [R0402]  119.55 76.38 270 top
R323  X  [R0402]  118.54 76.38 270 top
R324  4.7K  [R0402]  117.52 76.38 270 top
R325  4.7K  [R0402]  126.28 100.38 0 top
R326  X  [R0402]  126.28 98.35 0 top
R327  X  [R0402]  126.28 97.33 0 top
R328  X  [R0402]  126.28 101.4 0 top
R329  4.7K  [R0402]  126.28 99.37 0 top
R330  4.7K  [R0402]  126.28 96.32 0 top
R331  33  [R0402]  137.08 95.81 0 top
R332  33  [R0402]  137.08 94.79 0 top
R333  4.7K  [R0402]  136.57 100.64 270 top
R334  10K_1%  [R0402]  61.01 16.31 270 top
R335  10K_1%  [R0402]  63.29 16.31 270 top
R336  10K_1%  [R0402]  169.46 29.9 270 top
R337  10K_1%  [R0402]  171.75 29.9 270 top
R338  10K_1%  [R0402]  122.09 13.89 270 top
R339  10K_1%  [R0402]  124.38 16.31 270 top
R340  0  [R0402]  143.3 9.96 270 bottom
R341  10K_1%  [R0402]  142.29 9.96 270 bottom
R342  10K_1%  [R0402]  144.32 9.96 270 bottom
R343  10K_1%  [R0402]  143.3 4.62 90 bottom
R344  0  [R0402]  144.32 4.62 90 bottom
R345  100  [R0402]  107.74 45.26 180 top
R346  100  [R0402]  107.74 44.25 180 top
R347  0  [R0402]  92.5 54.92 270 top
R348  0  [R0402]  91.49 54.92 270 top
R349  2m_1%  [R2512]  119.43 32.18 270 top
R350  100  [R0402]  124.13 39.93 0 top
R351  100  [R0402]  124.13 38.91 0 top
R352  0  [R0402]  92.25 61.27 270 bottom
R353  0  [R0402]  93.26 61.27 270 bottom
R354  100  [R0402]  121.71 45.78 270 top
R355  100  [R0402]  122.73 45.78 270 top
R356  0  [R0402]  94.15 51.36 0 top
R357  0  [R0402]  94.15 52.38 0 top
R358  100  [R0402]  125.9 50.47 0 top
R359  100  [R0402]  125.9 51.49 0 top
R360  0  [R0402]  113.71 96.57 0 top
R361  0  [R0402]  113.71 95.56 0 top
R362  100  [R0402]  76.88 37.77 0 top
R363  100  [R0402]  76.88 36.63 0 top
R364  0  [R0402]  29.76 87.17 180 bottom
R365  0  [R0402]  29.76 88.19 180 bottom
R366  100  [R0402]  66.47 31.42 90 top
R367  100  [R0402]  65.45 31.42 90 top
R368  124_1%  [R0603]  6.52 48.44 180 bottom
R369  0  [R0402]  6.4 49.96 0 bottom
R370  0  [R0402]  133.9 114.99 0 top
R371  0  [R0402]  133.9 113.97 0 top
R372  0  [R0402]  144.19 147.75 270 bottom
R373  X  [R0402]  144.19 150.04 90 bottom
R374  0  [R0402]  131.62 113.97 0 top
R375  X  [R0402]  149.27 150.04 90 bottom
R376  0  [R0402]  131.62 116.13 0 top
R377  0  [R0402]  133.9 116.13 0 top
R378  2.2K  [R0402]  148.51 133.91 180 bottom
R379  120_1%  [R0402]  144.19 143.43 0 bottom
R380  120_1%  [R0402]  141.78 143.43 180 bottom
R381  120_1%  [R0402]  150.8 134.93 0 bottom
R382  120_1%  [R0402]  150.8 133.91 180 bottom
R383  120_1%  [R0402]  145.84 136.2 0 bottom
R384  120_1%  [R0402]  143.56 136.2 180 bottom
R385  120_1%  [R0402]  153.34 147.75 270 bottom
R386  120_1%  [R0402]  153.34 150.04 90 bottom
R387  120_1%  [R0402]  154.35 147.75 270 bottom
R388  120_1%  [R0402]  154.35 150.04 90 bottom
R389  120_1%  [R0402]  155.37 147.75 270 bottom
R390  120_1%  [R0402]  155.37 150.04 90 bottom
R391  120_1%  [R0402]  151.3 147.75 270 bottom
R392  120_1%  [R0402]  151.3 150.04 90 bottom
R393  120_1%  [R0402]  144.19 141.4 0 bottom
R394  120_1%  [R0402]  141.78 141.4 180 bottom
R395  120_1%  [R0402]  152.32 147.75 270 bottom
R396  120_1%  [R0402]  152.32 150.04 90 bottom
R397  120_1%  [R0402]  143.18 147.75 270 bottom
R398  120_1%  [R0402]  143.18 150.04 90 bottom
R399  120_1%  [R0402]  144.19 138.35 0 bottom
R400  120_1%  [R0402]  141.78 138.35 180 bottom
R401  120_1%  [R0402]  145.21 147.75 270 bottom
R402  120_1%  [R0402]  145.21 150.04 90 bottom
R403  X  [R0402]  133.9 112.95 0 top
R404  120_1%  [R0402]  144.19 142.42 0 bottom
R405  120_1%  [R0402]  141.78 142.42 180 bottom
R406  X  [R0402]  131.62 112.95 0 top
R407  120_1%  [R0402]  150.29 147.75 270 bottom
R408  120_1%  [R0402]  150.29 150.04 90 bottom
R409  120_1%  [R0402]  145.84 135.18 0 bottom
R410  120_1%  [R0402]  143.56 135.18 180 bottom
R411  120_1%  [R0402]  148.26 147.75 270 bottom
R412  120_1%  [R0402]  148.26 150.04 90 bottom
R413  120_1%  [R0402]  144.19 139.37 0 bottom
R414  120_1%  [R0402]  141.78 139.37 180 bottom
R415  120_1%  [R0402]  147.24 147.75 270 bottom
R416  120_1%  [R0402]  147.24 150.04 90 bottom
R417  120_1%  [R0402]  144.19 140.39 0 bottom
R418  120_1%  [R0402]  141.78 140.39 180 bottom
R419  120_1%  [R0402]  144.19 145.47 0 bottom
R420  120_1%  [R0402]  141.78 145.47 180 bottom
R421  120_1%  [R0402]  146.22 147.75 270 bottom
R422  120_1%  [R0402]  146.22 150.04 90 bottom
R423  120_1%  [R0402]  144.19 144.45 0 bottom
R424  120_1%  [R0402]  141.78 144.45 180 bottom
R425  120_1%  [R0402]  144.19 137.34 0 bottom
R426  120_1%  [R0402]  141.78 137.34 180 bottom
R427  120_1%  [R0402]  156.38 147.75 270 bottom
R428  120_1%  [R0402]  156.38 150.04 90 bottom
R429  240_1%  [R0402]  145.21 127.05 270 bottom
R430  60.4_1%  [R0402]  152.45 140.01 90 bottom
R431  33  [R0402]  131.62 111.94 180 top
R432  33  [R0402]  139.75 105.84 270 top
R433  60.4_1%  [R0402]  153.46 140.01 90 bottom
R434  33  [R0402]  133.9 110.92 180 top
R435  33  [R0402]  133.9 111.94 180 top
R436  0  [R0402]  133.9 114.99 180 bottom
R437  0  [R0402]  105.33 124 180 bottom
R438  X  [R0402]  133.9 113.97 180 bottom
R439  X  [R0402]  131.62 113.97 180 bottom
R440  0  [R0402]  133.9 116.13 180 bottom
R441  4.7K  [R0402]  133.9 117.27 180 bottom
R442  0  [R0402]  131.62 118.29 180 bottom
R443  4.7K  [R0402]  131.62 117.27 0 bottom
R444  0  [R0402]  131.62 114.99 180 top
R445  0  [R0402]  131.62 120.7 180 bottom
R454  1K  [R0402]  141.78 148.51 0 top
R455  0  [R0402]  161.21 120.19 0 top
R456  0  [R0402]  161.21 122.61 0 top
R457  0  [R0402]  163.75 123.62 0 top
R458  240_1%  [R0402]  156.51 135.81 90 bottom
R459  0  [R0402]  161.21 123.62 0 top
R460  0  [R0402]  141.91 105.84 270 bottom
R461  0  [R0402]  143.94 105.84 270 top
R462  0  [R0402]  131.62 118.42 180 top
R463  0  [R0402]  133.9 118.42 180 top
R464  1K  [R0402]  141.78 149.53 180 top
R465  4.7K  [R0402]  131.62 119.56 180 bottom
R467  4.7K  [R0402]  131.62 114.99 180 bottom
R468  4.7K  [R0402]  131.62 116.13 180 bottom
R470  4.7K  [R0402]  131.62 117.27 0 top
R472  4.7K  [R0402]  133.9 117.27 180 top
R473  4.7K  [R0402]  161.21 121.21 180 top
R475  4.7K  [R0402]  163.75 122.61 0 top
R480  0  [R0402]  135.05 133.27 180 bottom
R481  0  [R0402]  135.05 134.29 180 bottom
R482  0  [R0402]  131.62 125.27 180 bottom
R483  2.2K  [R0402]  119.81 136.07 270 bottom
R484  2.2K  [R0402]  122.35 129.08 90 bottom
R485  2.2K  [R0402]  128.06 143.82 180 bottom
R486  0  [R0402]  133.9 124.13 180 bottom
R487  2.2K  [R0402]  133.9 130.99 0 top
R488  0  [R0402]  133.9 122.99 180 bottom
R489  2.2K  [R0402]  133.9 129.85 0 top
R490  X  [R0402]  133.9 120.7 180 top
R491  X  [R0402]  131.62 120.7 180 top
R492  0  [R0402]  131.62 130.99 180 top
R493  0  [R0402]  163.75 125.65 180 top
R494  0  [R0402]  163.75 126.67 180 top
R495  0  [R0402]  131.62 126.42 180 bottom
R496  X  [R0402]  133.9 119.56 180 top
R497  X  [R0402]  131.62 119.56 180 top
R498  0  [R0402]  131.62 129.85 180 top
R499  X  [R0402]  133.9 129.85 180 bottom
R500  X  [R0402]  131.62 127.56 180 top
R501  X  [R0402]  131.62 128.7 180 top
R502  X  [R0402]  133.9 127.56 180 top
R503  4.7K  [R0402]  133.9 126.42 180 top
R504  4.7K  [R0402]  133.9 124.13 180 top
R505  4.7K  [R0402]  133.9 121.84 0 bottom
R506  4.7K  [R0402]  131.62 125.27 180 top
R507  4.7K  [R0402]  133.9 120.7 0 bottom
R508  4.7K  [R0402]  131.62 126.42 180 top
R509  4.7K  [R0402]  131.62 121.84 180 top
R510  4.7K  [R0402]  133.9 121.84 180 top
R511  4.7K  [R0402]  133.9 118.42 180 bottom
R512  4.7K  [R0402]  133.9 119.56 180 bottom
R513  0  [R0402]  163.75 124.64 180 top
R514  0  [R0402]  157.65 123.5 180 bottom
R515  0  [R0402]  161.21 124.64 180 top
R516  0  [R0402]  155.75 125.79 270 bottom
R517  0  [R0402]  157.66 125.53 180 bottom
R518  0  [R0402]  157.66 124.51 180 bottom
R519  2.2K  [R0402]  119.3 142.16 180 top
R520  2.2K  [R0402]  135.05 135.31 0 top
R521  22  [R0402]  158.67 107.49 0 bottom
R522  22  [R0402]  156.38 105.84 270 top
R523  22  [R0402]  144.95 105.84 270 bottom
R524  4.7K  [R0402]  143.94 105.84 270 bottom
R525  4.7K  [R0402]  148 105.84 270 bottom
R526  4.7K  [R0402]  156.38 105.84 90 bottom
R527  X  [R0402]  131.62 121.84 180 bottom
R528  4.7K  [R0402]  133.9 122.99 0 top
R529  X  [R0402]  133.9 128.7 180 bottom
R530  X  [R0402]  131.62 124.13 0 top
R531  X  [R0402]  133.9 126.42 180 bottom
R532  X  [R0402]  131.62 122.99 0 top
R533  4.7K  [R0402]  133.9 128.7 180 top
R534  4.7K  [R0402]  133.9 125.27 0 top
R535  0  [R0402]  133.9 127.56 0 bottom
R536  0  [R0402]  131.62 128.7 0 bottom
R537  10K_1%  [R0402]  161.21 119.18 180 top
R538  0  [R0402]  152.07 105.84 270 top
R539  0  [R0402]  151.05 105.84 270 top
R541  X  [R0402]  157.65 128.58 0 bottom
R542  X  [R0402]  157.65 127.56 0 bottom
R543  X  [R0402]  161.21 127.69 0 top
R544  X  [R0402]  161.21 126.67 180 top
R545  X  [R0402]  161.21 129.72 180 top
R546  X  [R0402]  161.21 130.73 180 top
R547  X  [R0402]  161.21 130.73 180 bottom
R548  8.2K  [R0402]  150.03 105.84 270 top
R549  8.2K  [R0402]  153.08 105.84 270 top
R550  10  [R0402]  139.75 130.99 270 bottom
R551  560  [R0402]  137.46 133.91 180 bottom
R552  10K_1%  [R0402]  138.73 130.99 270 bottom
R553  X  [R0402]  140.89 105.84 270 top
R554  4.7K  [R0402]  141.91 105.84 270 top
R555  4.7K  [R0402]  142.92 105.84 270 top
R556  4.7K  [R0402]  140.89 105.84 270 bottom
R557  4.7K  [R0402]  157.65 126.54 0 bottom
R558  4.7K  [R0402]  161.21 128.7 0 top
R559  4.7K  [R0402]  161.21 131.75 0 bottom
R560  4.7K  [R0402]  157.65 129.59 0 bottom
R561  X  [R0402]  142.92 105.84 270 bottom
R562  X  [R0402]  144.95 105.84 270 top
R563  X  [R0402]  151.05 105.84 270 bottom
R564  X  [R0402]  146.99 105.84 270 top
R565  X  [R0402]  145.97 105.84 270 top
R566  3.3K_1%  [R0402]  148 105.84 90 top
R567  X  [R0402]  133.9 125.27 0 bottom
R568  3.3K_1%  [R0402]  157.4 105.84 90 bottom
R569  X  [R0402]  158.42 105.84 270 bottom
R570  3.3K_1%  [R0402]  131.62 124.13 0 bottom
R571  X  [R0402]  154.35 105.84 90 bottom
R572  3.3K_1%  [R0402]  155.37 105.84 270 bottom
